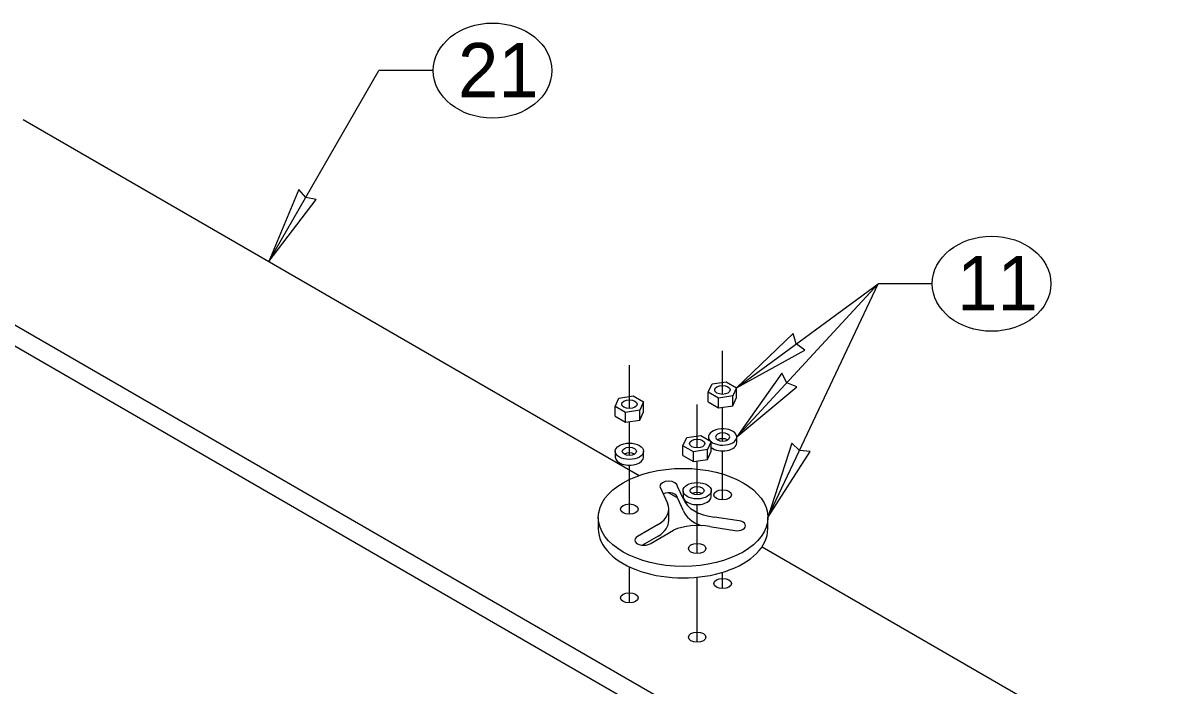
# Model space of a CAD drawing. Extents: x 99862 to 104211, y 98939 to 105076.
# Drawn here: x 101812.5 to 102152.3, y 103616.7 to 103812.1 of the extents above; entities that cross this region are included whole.
import ezdxf

# ---------------------------------------------------------------- set-up
doc = ezdxf.new("R2010")
doc.units = 0
for name, color, linetype in [('Level 11', 7, 'Continuous'), ('Level 12', 7, 'Continuous'), ('Level 15', 7, 'Continuous'), ('Level 20', 7, 'Continuous'), ('Level 21', 7, 'Continuous')]:
    doc.layers.add(name, color=color, linetype=linetype)

msp = doc.modelspace()

# ---------------------------------------------------------------- linework, layer by layer
at = {"layer": 'Level 11'}
for p, q in [((102014.6, 103703.35), (102015.72, 103705.76)), ((102015.72, 103705.76), (102019.9, 103706.41)), ((102019.9, 103706.41), (102022.96, 103704.64)), ((101988.28, 103701.55), (101992.46, 103702.2)), ((101992.46, 103702.2), (101995.52, 103700.43)), ((102014.6, 103700.44), (102014.6, 103703.35)), ((102017.66, 103701.58), (102014.6, 103703.35)), ((102021.84, 103702.22), (102017.66, 103701.58)), ((102022.96, 103704.64), (102021.84, 103702.22)), ((102021.84, 103699.31), (102021.84, 103702.22)), ((102022.96, 103701.73), (102022.96, 103704.64)), ((101987.16, 103699.14), (101988.28, 103701.55)), ((101987.16, 103696.23), (101987.16, 103699.14)), ((101990.22, 103697.37), (101987.16, 103699.14)), ((101995.52, 103700.43), (101994.4, 103698.02)), ((101995.52, 103697.52), (101995.52, 103700.43)), ((102014.6, 103700.44), (102017.66, 103698.67)), ((102017.66, 103698.67), (102017.66, 103701.58)), ((102017.66, 103698.67), (102021.84, 103699.31)), ((102021.84, 103699.31), (102022.96, 103701.73)), ((101987.16, 103696.23), (101990.22, 103694.46)), ((101994.4, 103698.02), (101990.22, 103697.37)), ((101990.22, 103694.46), (101990.22, 103697.37)), ((101994.4, 103695.11), (101994.4, 103698.02)), ((101994.4, 103695.11), (101995.52, 103697.52)), ((101990.22, 103694.46), (101994.4, 103695.11)), ((102007.14, 103687.53), (102008.26, 103689.94)), ((102008.26, 103689.94), (102012.45, 103690.59)), ((102012.45, 103690.59), (102015.51, 103688.82)), ((102015.51, 103688.82), (102014.39, 103686.41)), ((102014.68, 103690.11), (102014.68, 103689.3)), ((102015.51, 103685.91), (102015.51, 103688.82)), ((102023.02, 103688.41), (102023.02, 103690.11)), ((101987.17, 103685.9), (101987.17, 103684.2)), ((101995.51, 103684.2), (101995.51, 103685.9)), ((102007.14, 103684.62), (102007.14, 103687.53)), ((102010.21, 103685.76), (102007.14, 103687.53)), ((102014.39, 103686.41), (102010.21, 103685.76)), ((102010.21, 103682.85), (102010.21, 103685.76)), ((102014.39, 103683.5), (102014.39, 103686.41)), ((102014.39, 103683.5), (102015.51, 103685.91)), ((102007.14, 103684.62), (102010.21, 103682.85)), ((102010.21, 103682.85), (102014.39, 103683.5)), ((102000.33, 103675.57), (102002.55, 103670.61)), ((102007.31, 103671.75), (102005.54, 103675.57)), ((102007.31, 103668.35), (102005.54, 103672.16)), ((102007.16, 103674.29), (102007.16, 103672.59)), ((102015.49, 103672.59), (102015.49, 103674.29)), ((102002.95, 103665.47), (102002.95, 103668.87)), ((101982.18, 103666.42), (101982.18, 103663.02)), ((102023.02, 103665.47), (102016.41, 103666.5)), ((102032.18, 103663.02), (102032.18, 103666.42)), ((101999.87, 103664.33), (101993.74, 103660.79)), ((101997.43, 103658.66), (102004.35, 103662.66)), ((102015.11, 103663.69), (102023.02, 103662.47)), ((101999.87, 103660.92), (101995.22, 103658.24))]:
    msp.add_line(p, q, dxfattribs=at)
for centre, major_axis in [((102018.78, 103703.99), (2.27, 0)), ((101991.34, 103699.79), (2.27, 0)), ((102011.33, 103688.18), (2.27, 0)), ((101991.34, 103685.9), (-4.17, 0)), ((101991.34, 103685.9), (-2.08, 0)), ((102007.18, 103666.42), (-25, 0)), ((102011.33, 103674.29), (-4.17, 0)), ((102011.33, 103674.29), (-2.08, 0)), ((102018.85, 103673.07), (-2.6, 0)), ((101991.34, 103668.87), (-2.6, 0)), ((102011.33, 103657.26), (-2.6, 0))]:
    msp.add_ellipse(centre, major_axis=major_axis, ratio=0.57735, dxfattribs=at)
for centre, major_axis, start_param, end_param in [((102018.85, 103690.11), (-4.17, 0), 0.640708, 6.732556), ((102018.85, 103688.41), (-4.17, 0), 0.640708, 3.141593), ((102018.85, 103690.11), (-2.08, 0), 0.014662, 6.296698), ((102018.85, 103688.41), (-2.08, 0), 3.926991, 5.497787), ((101991.34, 103684.2), (-2.08, 0), 3.926991, 5.497787), ((101991.34, 103684.2), (-4.17, 0), 0, 3.141593), ((102002.94, 103675.57), (-2.6, 0), 3.141593, 6.283185), ((102002.94, 103672.16), (-2.6, 0), 3.141593, 5.379094), ((102011.33, 103672.59), (-4.17, 0), 6.283185, 9.424778), ((102018.78, 103673.12), (-11.71, 0), 0.203445, 1.367352), ((102011.33, 103672.59), (-2.08, 0), 3.926991, 5.497787), ((101991.34, 103668.87), (-11.61, 0), 2.396309, 3.403392), ((102018.78, 103669.71), (-11.71, 0), 0.203445, 1.005854), ((101991.34, 103665.47), (-11.61, 0), 2.396309, 3.141593), ((102023.02, 103663.97), (-2.6, 0), 1.570796, 4.712389), ((102007.18, 103663.02), (-25, 0), 6.283185, 9.424778), ((102011.43, 103657.27), (-11.71, 0), 4.392235, 5.361438), ((101995.58, 103659.72), (-2.6, 0), 5.497787, 8.63938)]:
    msp.add_ellipse(centre, major_axis=major_axis, ratio=0.57735, start_param=start_param, end_param=end_param, dxfattribs=at)
at = {"layer": 'Level 12'}
msp.add_line((102255.59, 103465.87), (101758.84, 103752.66), dxfattribs=at)
at = {"layer": 'Level 15'}
for p, q in [((101884.98, 103741.8), (101917.48, 103798.09)), ((101933.48, 103798.09), (101917.48, 103798.09)), ((102022.96, 103704.64), (102064.68, 103735.27)), ((102023.02, 103690.11), (102064.68, 103735.27)), ((102032.18, 103666.42), (102064.68, 103735.27)), ((102080.68, 103735.27), (102064.68, 103735.27)), ((102018.78, 103702.68), (102018.78, 103715.52)), ((101991.34, 103698.48), (101991.34, 103711.32)), ((102011.33, 103686.87), (102011.33, 103699.71)), ((102018.78, 103688.9), (102018.78, 103698.84)), ((101991.34, 103684.7), (101991.34, 103694.64)), ((102018.78, 103671.57), (102018.78, 103686)), ((101991.34, 103667.37), (101991.34, 103681.79)), ((102011.33, 103673.09), (102011.33, 103683.02)), ((102011.33, 103655.76), (102011.33, 103670.18)), ((101991.34, 103641.21), (101991.34, 103651.85)), ((102011.33, 103629.6), (102011.33, 103648.78)), ((102018.85, 103645.42), (102018.85, 103650.25))]:
    msp.add_line(p, q, dxfattribs=at)
for points in [[(101884.98, 103741.8), (101898.98, 103760.08), (101895.87, 103760.66), (101893.81, 103763.06)], [(102022.96, 103704.64), (102043.13, 103715.74), (102040.51, 103717.53), (102039.6, 103720.56)], [(102023.02, 103690.11), (102040.69, 103704.86), (102037.78, 103706.11), (102036.3, 103708.91)], [(102032.18, 103666.42), (102044.63, 103685.79), (102041.47, 103686.11), (102039.23, 103688.34)]]:
    msp.add_lwpolyline(points, close=True, dxfattribs=at)
at = {"layer": 'Level 20'}
for centre in [(101950.98, 103798.09), (102098.18, 103735.27)]:
    msp.add_ellipse(centre, major_axis=(-17.5, 0), ratio=0.8, dxfattribs=at)
at = {"layer": 'Level 21'}
for p, q in [((101812.51, 103783.64), (101994.19, 103678.75)), ((102255.59, 103459.67), (101758.84, 103746.47)), ((102002.99, 103673.67), (102005.54, 103672.2)), ((102030.49, 103657.79), (102269.42, 103519.84))]:
    msp.add_line(p, q, dxfattribs=at)
for centre in [(102018.85, 103646.92), (101991.34, 103642.72), (102011.33, 103631.11)]:
    msp.add_ellipse(centre, major_axis=(-2.6, 0), ratio=0.57735, dxfattribs=at)

# ---------------------------------------------------------------- texts
at = {"layer": 'Level 20'}
for s, p in [('21', (101940.79, 103790.22)), ('11', (102087.99, 103727.4))]:
    msp.add_text(s, height=16, dxfattribs=at).set_placement(p)

doc.saveas('drawing.dxf')
